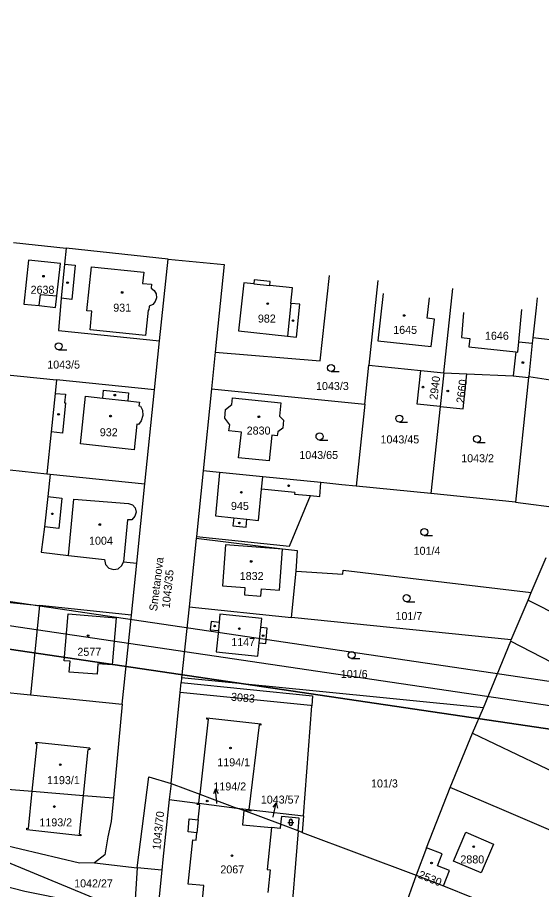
# Model space of a CAD drawing. Extents: x -779330 to -774454, y -1144748 to -1142831.
# Drawn here: x -775205.5 to -775094.2, y -1144366.8 to -1144181.6 of the extents above; entities that cross this region are included whole.
import ezdxf

# ---------------------------------------------------------------- set-up
doc = ezdxf.new("R2010")
doc.units = 0
for name, color, linetype in [('Hranice parcel', 7, 'Continuous'), ('Parcelní čísla', 7, 'Continuous'), ('Pop  PČ popisy', 7, 'Continuous'), ('Vnitřní kresba', 7, 'Continuous'), ('Vrstva 1', 7, 'Continuous'), ('Značky budov', 7, 'Continuous'), ('Značky kultur', 7, 'Continuous')]:
    doc.layers.add(name, color=color, linetype=linetype)

msp = doc.modelspace()

# ---------------------------------------------------------------- linework, layer by layer
at = {"layer": 'Hranice parcel'}
for p, q in [((-775206.34, -1144229.39), (-775195.14, -1144230.58)), ((-775173.49, -1144232.87), (-775195.14, -1144230.58)), ((-775175.3, -1144250.27), (-775173.49, -1144232.87)), ((-775173.49, -1144232.87), (-775161.61, -1144234.03)), ((-775161.61, -1144234.03), (-775163.5, -1144252.63)), ((-775129, -1144237.46), (-775130.88, -1144255.41)), ((-775114.97, -1144257.02), (-775113.08, -1144239.13)), ((-775176.38, -1144260.66), (-775175.3, -1144250.27)), ((-775163.5, -1144252.63), (-775164.29, -1144260.43)), ((-775131.75, -1144263.67), (-775130.88, -1144255.41)), ((-775130.88, -1144255.41), (-775119.85, -1144256.53)), ((-775119.85, -1144256.53), (-775114.97, -1144257.02)), ((-775208.99, -1144257.32), (-775197.16, -1144258.53)), ((-775114.97, -1144257.02), (-775115.73, -1144264.21)), ((-775114.97, -1144257.02), (-775110.05, -1144257.25)), ((-775096.95, -1144258.04), (-775099.74, -1144284.49)), ((-775096.95, -1144258.04), (-775096.93, -1144257.82)), ((-775176.38, -1144260.66), (-775197.16, -1144258.53)), ((-775178.41, -1144280.62), (-775176.38, -1144260.66)), ((-775164.29, -1144260.43), (-775166.06, -1144277.88)), ((-775164.29, -1144260.43), (-775131.75, -1144263.67)), ((-775131.75, -1144263.67), (-775133.58, -1144281.12)), ((-775115.73, -1144264.21), (-775117.69, -1144282.7)), ((-775227.98, -1144275.38), (-775199.27, -1144278.47)), ((-775199.27, -1144278.47), (-775198.56, -1144278.54)), ((-775198.56, -1144278.54), (-775178.41, -1144280.62)), ((-775166.06, -1144277.88), (-775167.48, -1144291.85)), ((-775180.15, -1144297.46), (-775178.41, -1144280.62)), ((-775117.69, -1144282.7), (-775133.58, -1144281.12)), ((-775099.74, -1144284.49), (-775117.69, -1144282.7)), ((-775099.74, -1144284.49), (-775089.18, -1144285.87)), ((-775167.52, -1144292.21), (-775169, -1144306.79)), ((-775167.48, -1144291.85), (-775167.52, -1144292.21)), ((-775096.39, -1144303.74), (-775093.25, -1144296.26)), ((-775181.29, -1144308.5), (-775180.15, -1144297.46)), ((-775147.28, -1144309), (-775146.29, -1144299.21)), ((-775239.94, -1144302.5), (-775200.81, -1144306.5)), ((-775097.05, -1144305.31), (-775096.39, -1144303.74)), ((-775200.81, -1144306.5), (-775202.71, -1144325.45)), ((-775181.29, -1144308.5), (-775200.81, -1144306.5)), ((-775100.66, -1144313.73), (-775097.05, -1144305.31)), ((-775097.05, -1144305.31), (-775056.83, -1144325.83)), ((-775169, -1144306.79), (-775170.62, -1144321.86)), ((-775169, -1144306.79), (-775147.28, -1144309)), ((-775183.24, -1144327.44), (-775181.29, -1144308.5)), ((-775100.66, -1144313.73), (-775147.28, -1144309)), ((-775100.74, -1144314.07), (-775100.66, -1144313.73)), ((-775106.56, -1144328.24), (-775100.74, -1144314.07)), ((-775100.74, -1144314.07), (-775062.91, -1144333.66)), ((-775170.93, -1144324.96), (-775170.72, -1144322.85)), ((-775170.62, -1144321.86), (-775170.72, -1144322.85)), ((-775210.05, -1144324.7), (-775202.71, -1144325.45)), ((-775172.87, -1144344.25), (-775170.93, -1144324.96)), ((-775202.71, -1144325.45), (-775183.24, -1144327.44)), ((-775183.24, -1144327.44), (-775185.12, -1144347.36)), ((-775144.74, -1144351.18), (-775142.99, -1144327.77)), ((-775108.85, -1144333.58), (-775106.56, -1144328.24)), ((-775113.6, -1144345.1), (-775108.85, -1144333.58)), ((-775108.85, -1144333.58), (-775058.75, -1144357.6)), ((-775172.87, -1144344.25), (-775173.24, -1144347.7)), ((-775118.61, -1144357.98), (-775113.6, -1144345.1)), ((-775173.24, -1144347.7), (-775167.28, -1144348.44)), ((-775182.38, -1144371.44), (-775227.51, -1144352.79)), ((-775144.74, -1144351.18), (-775145, -1144354.68)), ((-775145.88, -1144354.35), (-775149.61, -1144352.95)), ((-775145, -1144354.68), (-775145.88, -1144354.35)), ((-775145, -1144354.68), (-775120.83, -1144363.72)), ((-775118.61, -1144357.98), (-775120.83, -1144363.72)), ((-775189.15, -1144361.13), (-775180.09, -1144362.23)), ((-775180.09, -1144362.23), (-775180.7, -1144372.14)), ((-775174.82, -1144362.68), (-775180.09, -1144362.23)), ((-775174.82, -1144362.68), (-775176.33, -1144377.47)), ((-775120.83, -1144363.72), (-775126.26, -1144378.82)), ((-775120.83, -1144363.72), (-775115.06, -1144366.03)), ((-775115.06, -1144366.03), (-775098.84, -1144372.52))]:
    msp.add_line(p, q, dxfattribs=at)
for points in [[(-775195.14, -1144230.58), (-775195.48, -1144233.94), (-775196.2, -1144241.22), (-775196.75, -1144248.04), (-775175.3, -1144250.27)], [(-775204.16, -1144242.43), (-775200.84, -1144242.75), (-775197.43, -1144243.15), (-775197.13, -1144240.7), (-775196.34, -1144233.82), (-775203.11, -1144233.08), (-775204.16, -1144242.43)], [(-775163.5, -1144252.63), (-775141.23, -1144254.49), (-775139.23, -1144236.38)], [(-775095.17, -1144241.09), (-775095.37, -1144243.24), (-775096.06, -1144249.61), (-775096.18, -1144250.74), (-775096.93, -1144257.82)], [(-775115.73, -1144264.21), (-775120.61, -1144263.7), (-775119.85, -1144256.53)], [(-775115.73, -1144264.21), (-775110.86, -1144264.73), (-775110.05, -1144257.25)], [(-775110.05, -1144257.25), (-775100.26, -1144257.7), (-775096.95, -1144258.04)], [(-775096.93, -1144257.82), (-775087.72, -1144259.21), (-775078.9, -1144260.93)], [(-775197.16, -1144258.53), (-775197.47, -1144261.44), (-775198.33, -1144269.61), (-775199.27, -1144278.47)], [(-775160.42, -1144268.06), (-775161.48, -1144266.65), (-775161.29, -1144264.87), (-775159.98, -1144263.77), (-775159.83, -1144262.39), (-775149.57, -1144263.43), (-775149.88, -1144266.24), (-775149, -1144267.11), (-775149.17, -1144268.77), (-775150.23, -1144269.55), (-775150.33, -1144270.42), (-775151.46, -1144270.3), (-775152.06, -1144275.77), (-775158.52, -1144275.09), (-775157.92, -1144269.65), (-775160.57, -1144269.36), (-775160.42, -1144268.06)], [(-775198.56, -1144278.54), (-775199.05, -1144283.3), (-775199.71, -1144289.78), (-775200.48, -1144295.17), (-775194.67, -1144295.88), (-775187.03, -1144296.72), (-775186.78, -1144297.78), (-775186.1, -1144298.53), (-775185.09, -1144298.85), (-775184.13, -1144298.65), (-775183.33, -1144297.99), (-775182.98, -1144297.17), (-775180.15, -1144297.46)], [(-775141.07, -1144280.37), (-775153.4, -1144279.14), (-775162.55, -1144278.22), (-775166.06, -1144277.88)], [(-775167.48, -1144291.85), (-775147.73, -1144293.87), (-775143.29, -1144283.14), (-775141.3, -1144283.35), (-775141.07, -1144280.37)], [(-775133.58, -1144281.12), (-775136.6, -1144280.82), (-775141.07, -1144280.37)], [(-775146.29, -1144299.21), (-775145.99, -1144294.86), (-775149.18, -1144294.5), (-775167.52, -1144292.21)], [(-775146.29, -1144299.21), (-775136.38, -1144299.82), (-775136.33, -1144298.95), (-775096.39, -1144303.74)], [(-775162.83, -1144311.77), (-775163.26, -1144316.34), (-775154.43, -1144317.26), (-775154.13, -1144314.43), (-775152.78, -1144314.57), (-775152.43, -1144311.26), (-775153.79, -1144311.12), (-775153.6, -1144309.26), (-775162.5, -1144308.34), (-775162.67, -1144310.05), (-775164.38, -1144309.89), (-775164.55, -1144311.61), (-775162.83, -1144311.77)], [(-775170.72, -1144322.85), (-775142.83, -1144325.63), (-775142.99, -1144327.77)], [(-775106.56, -1144328.24), (-775142.77, -1144324.63), (-775170.62, -1144321.86)], [(-775142.99, -1144327.77), (-775143.26, -1144327.74), (-775170.93, -1144324.96)], [(-775180.09, -1144362.23), (-775177.56, -1144342.89), (-775172.87, -1144344.25)], [(-775212.14, -1144345.14), (-775202.35, -1144345.94), (-775191.45, -1144346.84), (-775185.12, -1144347.36)], [(-775172.87, -1144344.25), (-775166.77, -1144346.53), (-775158.88, -1144349.49)], [(-775064.72, -1144366.06), (-775102.16, -1144350), (-775113.6, -1144345.1)], [(-775185.12, -1144347.36), (-775185.59, -1144352.33), (-775186.28, -1144355.64), (-775186.94, -1144359.43), (-775189.15, -1144361.13)], [(-775173.24, -1144347.7), (-775174.59, -1144360.4), (-775174.82, -1144362.68)], [(-775166.21, -1144369.09), (-775165.91, -1144365.97), (-775169.22, -1144365.64), (-775168.28, -1144356.26), (-775167.54, -1144356.34), (-775167.38, -1144354.77), (-775169.27, -1144354.58), (-775169, -1144351.79), (-775167.1, -1144351.98), (-775166.78, -1144348.79), (-775167.31, -1144348.74), (-775167.28, -1144348.44)], [(-775167.28, -1144348.44), (-775166.99, -1144348.48), (-775158.88, -1144349.49)], [(-775158.88, -1144349.49), (-775156.33, -1144349.8), (-775155.88, -1144349.86), (-775144.74, -1144351.18)], [(-775149.61, -1144352.95), (-775157.41, -1144350.01), (-775158.88, -1144349.49)], [(-775145.88, -1144354.35), (-775147.65, -1144376.02), (-775149.68, -1144379.44), (-775151.47, -1144380.29), (-775171.96, -1144377.97), (-775176.33, -1144377.47)], [(-775149.61, -1144352.95), (-775149.7, -1144353.84), (-775151.54, -1144353.66), (-775152.43, -1144362.55), (-775151.85, -1144362.61), (-775152.33, -1144367.47)], [(-775104.42, -1144357.14), (-775107.06, -1144363.28), (-775112.91, -1144360.76), (-775110.28, -1144354.62), (-775104.42, -1144357.14)], [(-775189.15, -1144361.13), (-775192.34, -1144361.18), (-775213.28, -1144356.23)], [(-775115.06, -1144366.03), (-775113.75, -1144362.76), (-775116.27, -1144361.75), (-775115.34, -1144359.25), (-775118.61, -1144357.98)], [(-775241.44, -1144360.01), (-775230.77, -1144362.69), (-775229.2, -1144363.12), (-775220.08, -1144365.37), (-775209.29, -1144367.97), (-775208.86, -1144365.9), (-775203.92, -1144367.13), (-775193.75, -1144369.24), (-775184.75, -1144371.03), (-775182.38, -1144371.44)]]:
    msp.add_lwpolyline(points, dxfattribs=at)
at = {"layer": 'Pop  PČ popisy'}
for p, q in [((-775163.45, -1144345.45), (-775163.85, -1144346.49)), ((-775163.14, -1144348.43), (-775163.45, -1144345.45)), ((-775163.45, -1144345.45), (-775162.85, -1144346.39)), ((-775163.13, -1144348.51), (-775163.14, -1144348.43)), ((-775150.58, -1144348.42), (-775151.27, -1144349.29)), ((-775151.2, -1144351.35), (-775150.58, -1144348.42)), ((-775150.58, -1144348.42), (-775150.29, -1144349.5)), ((-775151.22, -1144351.46), (-775151.2, -1144351.35))]:
    msp.add_line(p, q, dxfattribs=at)
at = {"layer": 'Vnitřní kresba'}
for p, q in [((-775195.48, -1144233.94), (-775193.2, -1144234.17)), ((-775193.2, -1144234.17), (-775193.94, -1144241.5)), ((-775190.74, -1144243.86), (-775189.77, -1144234.52)), ((-775189.77, -1144234.52), (-775178.68, -1144235.68)), ((-775178.68, -1144235.68), (-775178.93, -1144238.05)), ((-775157.43, -1144237.92), (-775158.54, -1144248.13)), ((-775155.31, -1144238.14), (-775157.43, -1144237.92)), ((-775155.22, -1144237.28), (-775155.31, -1144238.14)), ((-775151.84, -1144237.64), (-775155.22, -1144237.28)), ((-775151.93, -1144238.49), (-775151.84, -1144237.64)), ((-775178.93, -1144238.05), (-775177, -1144238.22)), ((-775177, -1144238.22), (-775177.08, -1144239.09)), ((-775177.08, -1144239.09), (-775176.42, -1144239.58)), ((-775176.42, -1144239.58), (-775176.05, -1144240.3)), ((-775155.31, -1144238.14), (-775151.93, -1144238.49)), ((-775147.1, -1144239), (-775151.93, -1144238.49)), ((-775147.45, -1144242.33), (-775147.1, -1144239)), ((-775200.84, -1144242.75), (-775200.58, -1144240.4)), ((-775200.58, -1144240.4), (-775197.13, -1144240.7)), ((-775193.94, -1144241.5), (-775196.2, -1144241.22)), ((-775175.97, -1144241.09), (-775176.22, -1144241.89)), ((-775176.05, -1144240.3), (-775175.97, -1144241.09)), ((-775127.86, -1144240.19), (-775128.98, -1144250.27)), ((-775118.46, -1144245.46), (-775117.99, -1144241.14)), ((-775177.51, -1144242.87), (-775177.61, -1144243.73)), ((-775176.76, -1144242.51), (-775177.51, -1144242.87)), ((-775176.22, -1144241.89), (-775176.76, -1144242.51)), ((-775147.45, -1144242.33), (-775148.12, -1144249.24)), ((-775145.51, -1144242.48), (-775147.45, -1144242.33)), ((-775146.23, -1144249.44), (-775145.51, -1144242.48)), ((-775099.06, -1144250.43), (-775098.37, -1144243.56)), ((-775189.69, -1144243.97), (-775190.74, -1144243.86)), ((-775190.04, -1144247.9), (-775189.69, -1144243.97)), ((-775177.75, -1144243.72), (-775178.31, -1144249.11)), ((-775177.61, -1144243.73), (-775177.75, -1144243.72)), ((-775110.77, -1144244.25), (-775111.24, -1144249.57)), ((-775116.97, -1144245.62), (-775118.46, -1144245.46)), ((-775117.61, -1144251.47), (-775116.97, -1144245.62)), ((-775178.31, -1144249.11), (-775190.04, -1144247.9)), ((-775158.54, -1144248.13), (-775148.12, -1144249.24)), ((-775148.12, -1144249.24), (-775146.23, -1144249.44)), ((-775128.98, -1144250.27), (-775117.61, -1144251.47)), ((-775111.24, -1144249.57), (-775109.46, -1144249.76)), ((-775109.46, -1144249.76), (-775109.65, -1144251.53)), ((-775099.28, -1144252.65), (-775099.06, -1144250.43)), ((-775099.06, -1144250.43), (-775096.18, -1144250.74)), ((-775087.57, -1144250.58), (-775096.06, -1144249.61)), ((-775109.65, -1144251.53), (-775099.67, -1144252.61)), ((-775099.67, -1144252.61), (-775100.26, -1144257.7)), ((-775099.67, -1144252.61), (-775099.28, -1144252.65)), ((-775197.47, -1144261.44), (-775195.31, -1144261.61)), ((-775195.31, -1144261.61), (-775195.48, -1144263.4)), ((-775192.07, -1144272.16), (-775191.01, -1144262.02)), ((-775191.01, -1144262.02), (-775187.37, -1144262.41)), ((-775187.37, -1144262.41), (-775187.19, -1144260.74)), ((-775187.19, -1144260.74), (-775181.88, -1144261.31)), ((-775181.88, -1144261.31), (-775182.06, -1144262.98)), ((-775195.28, -1144263.42), (-775195.91, -1144269.85)), ((-775195.48, -1144263.4), (-775195.28, -1144263.42)), ((-775187.37, -1144262.41), (-775182.06, -1144262.98)), ((-775182.06, -1144262.98), (-775179.58, -1144263.25)), ((-775179.58, -1144263.25), (-775179.68, -1144264.07)), ((-775179.68, -1144264.07), (-775179.38, -1144264.11)), ((-775179.38, -1144264.11), (-775178.95, -1144265)), ((-775178.95, -1144265), (-775178.86, -1144266.12)), ((-775179.2, -1144267.22), (-775179.81, -1144268.01)), ((-775178.86, -1144266.12), (-775179.2, -1144267.22)), ((-775180.11, -1144267.98), (-775180.71, -1144273.43)), ((-775179.81, -1144268.01), (-775180.11, -1144267.98)), ((-775195.91, -1144269.85), (-775198.33, -1144269.61)), ((-775180.71, -1144273.43), (-775192.07, -1144272.16)), ((-775162.55, -1144278.22), (-775163.46, -1144287.42)), ((-775153.64, -1144281.75), (-775153.4, -1144279.14)), ((-775154.27, -1144288.43), (-775153.64, -1144281.75)), ((-775146.6, -1144282.49), (-775153.64, -1144281.75)), ((-775146.6, -1144282.49), (-775146.63, -1144282.79)), ((-775199.05, -1144283.3), (-775196.04, -1144283.64)), ((-775196.04, -1144283.64), (-775196.7, -1144290.09)), ((-775194.67, -1144295.88), (-775193.51, -1144283.85)), ((-775193.51, -1144283.85), (-775181.9, -1144284.84)), ((-775146.63, -1144282.79), (-775143.29, -1144283.14)), ((-775181.9, -1144284.84), (-775181.06, -1144285.1)), ((-775181.06, -1144285.1), (-775180.48, -1144285.72)), ((-775180.48, -1144285.72), (-775180.26, -1144286.63)), ((-775180.54, -1144287.49), (-775181.23, -1144288.26)), ((-775180.26, -1144286.63), (-775180.54, -1144287.49)), ((-775163.46, -1144287.42), (-775159.54, -1144287.85)), ((-775159.54, -1144287.85), (-775159.73, -1144289.55)), ((-775159.54, -1144287.85), (-775156.75, -1144288.16)), ((-775196.7, -1144290.09), (-775199.71, -1144289.78)), ((-775182.14, -1144288.26), (-775182.98, -1144297.17)), ((-775181.23, -1144288.26), (-775182.14, -1144288.26)), ((-775159.73, -1144289.55), (-775156.93, -1144289.86)), ((-775156.93, -1144289.86), (-775156.75, -1144288.16)), ((-775156.75, -1144288.16), (-775154.27, -1144288.43)), ((-775161.33, -1144293.6), (-775161.98, -1144302.32)), ((-775149.18, -1144294.5), (-775161.33, -1144293.6)), ((-775149.82, -1144303.23), (-775149.18, -1144294.5)), ((-775161.98, -1144302.32), (-775157.17, -1144302.67)), ((-775157.17, -1144302.67), (-775157.28, -1144304.21)), ((-775157.28, -1144304.21), (-775153.78, -1144304.49)), ((-775153.78, -1144304.49), (-775153.67, -1144302.95)), ((-775153.67, -1144302.95), (-775149.82, -1144303.23)), ((-775195.58, -1144318.22), (-775194.73, -1144308.23)), ((-775194.73, -1144308.23), (-775184.49, -1144309.11)), ((-775184.49, -1144309.11), (-775185.39, -1144319.09)), ((-775162.67, -1144310.05), (-775162.83, -1144311.77)), ((-775154.13, -1144314.43), (-775153.79, -1144311.12)), ((-775194.28, -1144318.33), (-775195.58, -1144318.22)), ((-775194.48, -1144320.63), (-775194.28, -1144318.33)), ((-775188.39, -1144318.83), (-775188.58, -1144321.08)), ((-775185.39, -1144319.09), (-775188.39, -1144318.83)), ((-775188.58, -1144321.08), (-775194.48, -1144320.63)), ((-775164.99, -1144330.62), (-775166.77, -1144346.53)), ((-775165.29, -1144330.59), (-775165.26, -1144330.32)), ((-775164.99, -1144330.62), (-775165.29, -1144330.59)), ((-775165.26, -1144330.32), (-775153.8, -1144331.6)), ((-775154.13, -1144331.83), (-775156.33, -1144349.8)), ((-775153.83, -1144331.87), (-775154.13, -1144331.83)), ((-775153.8, -1144331.6), (-775153.83, -1144331.87)), ((-775202.35, -1144345.94), (-775201.31, -1144335.87)), ((-775201.61, -1144335.84), (-775201.58, -1144335.54)), ((-775201.31, -1144335.87), (-775201.61, -1144335.84)), ((-775190.11, -1144336.77), (-775201.58, -1144335.54)), ((-775191.45, -1144346.84), (-775190.44, -1144337.04)), ((-775190.14, -1144337.07), (-775190.44, -1144337.04)), ((-775190.11, -1144336.77), (-775190.14, -1144337.07)), ((-775203.16, -1144353.83), (-775202.35, -1144345.94)), ((-775192.3, -1144355.09), (-775191.45, -1144346.84)), ((-775166.99, -1144348.48), (-775166.77, -1144346.53)), ((-775157.41, -1144350.01), (-775157.71, -1144353.04)), ((-775155.91, -1144350.16), (-775157.41, -1144350.01)), ((-775155.88, -1144349.86), (-775155.91, -1144350.16)), ((-775167.1, -1144351.98), (-775167.38, -1144354.77)), ((-775149.44, -1144351.26), (-775149.61, -1144352.95)), ((-775145.66, -1144351.63), (-775149.44, -1144351.26)), ((-775145.88, -1144354.35), (-775145.66, -1144351.63)), ((-775203.49, -1144354.09), (-775203.46, -1144353.79)), ((-775192.03, -1144355.42), (-775203.49, -1144354.09)), ((-775203.46, -1144353.79), (-775203.16, -1144353.83)), ((-775157.71, -1144353.04), (-775151.54, -1144353.66)), ((-775192.3, -1144355.09), (-775192, -1144355.12)), ((-775192, -1144355.12), (-775192.03, -1144355.42))]:
    msp.add_line(p, q, dxfattribs=at)
at = {"layer": 'Vrstva 1'}
for points in [[(-774799.29, -1144366.04), (-776045.7, -1144181.56), (-776089.18, -1144475.34), (-774842.77, -1144659.83)], [(-774846.98, -1144654.15), (-776083.5, -1144471.13), (-776041.48, -1144187.23), (-774804.97, -1144370.25)], [(-774810.64, -1144374.46), (-775834.48, -1144222.92), (-775875.04, -1144496.94), (-774851.19, -1144648.48)], [(-774851.19, -1144648.48), (-775875.04, -1144496.94), (-775834.48, -1144222.92), (-774810.64, -1144374.46)]]:
    msp.add_lwpolyline(points, close=True, dxfattribs=at)
at = {"layer": 'Značky budov'}
for centre in [(-775199.95, -1144236.53), (-775194.85, -1144237.88), (-775183.25, -1144239.98), (-775152.34, -1144242.34), (-775123.37, -1144244.87), (-775146.98, -1144245.96), (-775098.17, -1144254.87), (-775119.39, -1144260.09), (-775184.81, -1144261.78), (-775114.12, -1144260.9), (-775196.76, -1144265.87), (-775185.72, -1144266.25), (-775154.23, -1144266.39), (-775157.94, -1144282.43), (-775147.9, -1144281.04), (-775198.09, -1144287), (-775188, -1144289.28), (-775158.37, -1144288.94), (-775155.85, -1144297.11), (-775163.62, -1144310.83), (-775158.37, -1144311.41), (-775190.48, -1144312.89), (-775153.32, -1144312.87), (-775160.25, -1144336.75), (-775196.38, -1144340.3), (-775197.64, -1144349.18), (-775165.19, -1144348.01), (-775108.61, -1144357.71), (-775159.94, -1144359.62), (-775117.56, -1144361.17)]:
    msp.add_circle(centre, 0.175, dxfattribs=at)
at = {"layer": 'Značky kultur'}
for p, q in [((-775196.74, -1144252.16), (-775194.99, -1144252.16)), ((-775138.91, -1144256.77), (-775137.16, -1144256.77)), ((-775124.39, -1144267.52), (-775122.64, -1144267.52)), ((-775141.34, -1144271.32), (-775139.59, -1144271.32)), ((-775107.9, -1144271.86), (-775106.15, -1144271.86)), ((-775119.11, -1144291.61), (-775117.36, -1144291.61)), ((-775122.86, -1144305.67), (-775121.11, -1144305.67)), ((-775134.53, -1144317.74), (-775132.78, -1144317.74)), ((-775148.11, -1144352.55), (-775146.77, -1144352.55)), ((-775147.78, -1144352.22), (-775147.78, -1144352.89)), ((-775147.1, -1144352.89), (-775147.1, -1144352.22))]:
    msp.add_line(p, q, dxfattribs=at)
for centre in [(-775196.74, -1144251.41), (-775138.91, -1144256.02), (-775124.39, -1144266.77), (-775141.34, -1144270.57), (-775107.9, -1144271.11), (-775119.11, -1144290.86), (-775122.86, -1144304.92), (-775134.53, -1144316.99)]:
    msp.add_circle(centre, 0.75, dxfattribs=at)
for centre, start, end in [((-775147.44, -1144352.22), 0, 180), ((-775147.44, -1144352.89), 180, 359.9879)]:
    msp.add_arc(centre, 0.335, start, end, dxfattribs=at)

# ---------------------------------------------------------------- texts
at = {"layer": 'Parcelní čísla'}
for s, p in [('2638', (-775202.69, -1144240.25)), ('931', (-775185.14, -1144244.06)), ('982', (-775154.43, -1144246.37)), ('1645', (-775125.7, -1144248.77)), ('1646', (-775106.22, -1144250.02)), ('1043/5', (-775199.15, -1144256.15)), ('1043/3', (-775142.09, -1144260.7)), ('932', (-775187.99, -1144270.52)), ('2830', (-775156.81, -1144270.16)), ('1043/45', (-775128.4, -1144272.04)), ('1043/65', (-775145.63, -1144275.35)), ('1043/2', (-775111.26, -1144276.04)), ('945', (-775160.15, -1144286.17)), ('1004', (-775190.28, -1144293.56)), ('101/4', (-775121.37, -1144295.7)), ('1832', (-775158.29, -1144301.06)), ('101/7', (-775125.22, -1144309.56)), ('1147', (-775160.09, -1144315.11)), ('2577', (-775192.75, -1144317.16)), ('101/6', (-775136.83, -1144321.87)), ('1194/1', (-775163.05, -1144340.63)), ('1193/1', (-775199.2, -1144344.42)), ('101/3', (-775130.41, -1144345.12)), ('1194/2', (-775163.87, -1144345.76)), ('1043/57', (-775153.81, -1144348.55)), ('1193/2', (-775200.82, -1144353.39)), ('2880', (-775111.44, -1144361.26)), ('2067', (-775162.4, -1144363.38)), ('1042/27', (-775193.44, -1144366.35))]:
    msp.add_text(s, height=1.7, dxfattribs=at).set_placement(p)
for s, rotation, p in [('2940', 83, (-775116.34, -1144262.86)), ('2660', 83, (-775110.64, -1144263.58)), ('1043/35', 84, (-775173.16, -1144307.13)), ('3083', 355, (-775160.2, -1144326.68)), ('1043/70', 84, (-775175.15, -1144358.45)), ('2530', 338, (-775120.53, -1144364.28))]:
    msp.add_text(s, height=1.7, rotation=rotation, dxfattribs=at).set_placement(p)
at = {"layer": 'Pop  PČ popisy'}
msp.add_text('Smetanova', height=1.7, rotation=83, dxfattribs=at).set_placement((-775175.85, -1144307.74))

doc.saveas('drawing.dxf')
